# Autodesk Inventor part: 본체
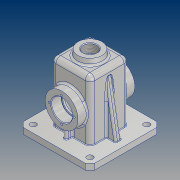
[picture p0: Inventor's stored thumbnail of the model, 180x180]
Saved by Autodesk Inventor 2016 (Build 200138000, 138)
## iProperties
Created: 2018-10
Part Number: 본체
Material: 알루미늄 6061
Document SubType Name: Modeling
Designer: user
Density: 2.7 g/cm^3
Appearance: 알루미늄 - 평지
Mass: 794.228 g
Surface Area: 899.5 cm^2
Volume: 294.158 cm^3
Author: user
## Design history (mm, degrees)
sketch "스케치1"
  geometry: L1 (-60, 60)-(60, 60); L2 (60, 60)-(60, -60); L3 (60, -60)-(-60, -60); L4 (-60, -60)-(-60, 60); L5 (-60, 60)-(60, -60); L6 (60, 60)-(-60, -60); 1 further point
  constraints: 12 end point, 2 midpoint, 2 parallel, 1 horizontal, 1 perpendicular
  dimensions: "d0" = 120 distance of L2.end L3.end; "d1" = 120 distance of L1.end L2.end
extrude "돌출1" new body sketch "스케치1" distance "d2" = 10; taper "d3" = 0 deg
sketch "스케치2"
  geometry: L1 (-32.5, -32.5)-(32.5, -32.5); L2 (32.5, -32.5)-(32.5, 32.5); L3 (32.5, 32.5)-(-32.5, 32.5); L4 (-32.5, 32.5)-(-32.5, -32.5); L5 (-32.5, -32.5)-(32.5, 32.5); L6 (32.5, -32.5)-(-32.5, 32.5); 1 further point
  constraints: 12 end point, 2 midpoint, 2 parallel, 1 horizontal, 1 perpendicular
  dimensions: "d4" = 65 distance of L3.end L2.end; "d5" = 65 distance of L2.end L1.end
extrude "돌출2" join sketch "스케치2" distance "d6" = 100; taper "d7" = 0 deg
feature "쉘1" dims "d8" = 10, "d9" = 5
sketch "스케치3"
  geometry: L1 (92.5, -10)-(-27.5, -10) reference; C1 r 27.5 at (32.5, 45); 2 further points
  constraints: 1 centre point, 1 midpoint, 1 vertical alignment
  dimensions: "d10" = 55 diameter of C1; "d11" = 55 distance from line of L1 C1.centre
extrude "돌출3" join sketch "스케치3" distance "d12" = 15; taper "d13" = 0 deg
sketch "스케치4" dims "d14" = 21
  geometry: C1 r 27.5 at (0, 0) reference; 3 further points
  constraints: 2 vertical alignment, 1 coincident, 2 other
hole "구멍1" sketch "스케치4" diameter "d15" = 30; stored, may be unused: countersink angle "d19" = 90 deg, drill point angle "d21" = 118 deg; dims "d16" = 6, "d17" = 35, "d18" = 17, "d20" = 8
hole "구멍2" sketch "스케치4" diameter "d22" = 3.242; stored, may be unused: countersink angle "d26" = 90 deg, drill point angle "d28" = 118 deg; dims "d23" = 8, "d24" = 35, "d25" = 17, "d27" = 10
node "작업 평면1"
sketch "스케치5"
  geometry: C1 r 20 at (0, 0); 1 further point
  constraints: 1 centre point, 1 coincident
  dimensions: "d33" = 20 radius of C1
extrude "돌출4" join sketch "스케치5" stored distance "d34" = 15; taper "d35" = 7 deg
sketch "스케치6"
  geometry: L1 (10, 48)-(97.905, 32.5); L2 (10, 32.5)-(110, 32.5) reference; L3 (10, -32.5)-(110, -32.5) reference; L4 (10, -60)-(10, 60) reference; L5 (0, 60)-(10, 60) reference; L6 (10, -32.5)-(110, -32.5) reference; L7 (97.905, -32.5)-(10, -48); L8 (0, -60)-(10, -60) reference; 1 further point
  constraints: 4 end point, 4 point on line
  dimensions: "d36" = 12 distance of L4.end L1.start; "d38" = 10 deg angle of L1 L5; "d82" = 12 distance from line of L8 L7.end; "d83" = 10 deg angle of L8 L7
feature "리브1" sketch "스케치6" dims "d39" = 1, "d40" = 10, "d41" = 0, "d42" = 0, "d43" = 1, "d44" = 1
sketch "스케치7"
  geometry: L1 (-42.5, 27.5)-(-42.5, 10); L2 (60, 10)-(-60, 10) reference; L3 (-27.5, 0)-(-27.5, 105) reference; L4 (-37.5, 32.379)-(-36.526, 34) reference; L5 (-36.526, 34)-(-37.5, 35.621) reference; L6 (-37.5, 35.621)-(-47.5, 35.621) reference; L7 (-47.5, 35.621)-(-47.5, 37.5) reference; L8 (-47.5, 37.5)-(-30.5, 37.5) reference; L9 (-30.5, 37.5)-(-30.5, 40) reference; L10 (-30.5, 40)-(-27.5, 40) reference; L11 (-27.5, 40)-(-27.5, 0) reference; L12 (-27.5, 0)-(-60, 0) reference; L13 (-60, 0)-(-60, 10) reference; L14 (-60, 10)-(-32.5, 10) reference; L15 (-32.5, 10)-(-32.5, 27.5) reference; L16 (-32.5, 27.5)-(-47.5, 27.5) reference; L17 (-47.5, 27.5)-(-47.5, 32.379) reference; L18 (-47.5, 32.379)-(-37.5, 32.379) reference; L19 (36.526, 34)-(37.5, 32.379) reference; L20 (37.5, 32.379)-(47.5, 32.379) reference; L21 (47.5, 32.379)-(47.5, 27.5) reference; L22 (47.5, 27.5)-(32.5, 27.5) reference; L23 (32.5, 27.5)-(32.5, 10) reference; L24 (32.5, 10)-(60, 10) reference; L25 (60, 10)-(60, 0) reference; L26 (60, 0)-(27.5, 0) reference; L27 (27.5, 0)-(27.5, 40) reference; L28 (27.5, 40)-(30.5, 40) reference; L29 (30.5, 40)-(30.5, 37.5) reference; L30 (30.5, 37.5)-(47.5, 37.5) reference; L31 (47.5, 37.5)-(47.5, 35.621) reference; L32 (47.5, 35.621)-(37.5, 35.621) reference; L33 (37.5, 35.621)-(36.526, 34) reference; L34 (37.5, 77.621)-(36.526, 76) reference; L35 (36.526, 76)-(37.5, 74.379) reference; L36 (37.5, 74.379)-(47.5, 74.379) reference; L37 (47.5, 74.379)-(47.5, 72.5) reference; L38 (47.5, 72.5)-(30.5, 72.5) reference; L39 (30.5, 72.5)-(30.5, 70) reference; L40 (30.5, 70)-(27.5, 70) reference; L41 (27.5, 70)-(27.5, 105) reference; L42 (27.5, 105)-(-27.5, 105) reference; L43 (-27.5, 105)-(-27.5, 70) reference; L44 (-27.5, 70)-(-30.5, 70) reference; L45 (-30.5, 70)-(-30.5, 72.5) reference; L46 (-30.5, 72.5)-(-47.5, 72.5) reference; L47 (-47.5, 72.5)-(-47.5, 74.379) reference; L48 (-47.5, 74.379)-(-37.5, 74.379) reference; L49 (-37.5, 74.379)-(-36.526, 76) reference; L50 (-36.526, 76)-(-37.5, 77.621) reference; L51 (-37.5, 77.621)-(-47.5, 77.621) reference; L52 (-47.5, 77.621)-(-47.5, 82.5) reference; L53 (-47.5, 82.5)-(-32.5, 82.5) reference; L54 (-32.5, 82.5)-(-32.5, 110) reference; L55 (-32.5, 110)-(-21.228, 110) reference; L56 (-21.228, 110)-(-20, 120) reference; L57 (-20, 120)-(20, 120) reference; L58 (20, 120)-(21.228, 110) reference; L59 (21.228, 110)-(32.5, 110) reference; L60 (32.5, 110)-(32.5, 82.5) reference; L61 (32.5, 82.5)-(47.5, 82.5) reference; L62 (47.5, 82.5)-(47.5, 77.621) reference; L63 (47.5, 77.621)-(37.5, 77.621) reference; 1 further point
  constraints: 2 end point, 2 point on line, 1 vertical
  dimensions: "d45" = 15 distance between parallel lines of L3 L1
feature "리브2" sketch "스케치7" dims "d46" = 1, "d47" = 6, "d48" = 0, "d49" = 0, "d50" = 1, "d51" = 1
sketch "스케치8"
  geometry: C1 r 20 at (0, 0) reference
hole "구멍3" sketch "스케치8" at (0, 0) diameter "d52" = 22.835; stored, may be unused: countersink angle "d56" = 90 deg, drill point angle "d58" = 118 deg; dims "d53" = 50, "d54" = 35, "d55" = 17, "d57" = 59.3
chamfer "모따기1" distance "d59" = 8; stored, may be unused: second distance "d60" = 2, angle "d61" = 45 deg
sketch "스케치9"
  geometry: L1 (-60, 52)-(-60, -52) reference; L2 (52, 60)-(-52, 60) reference; L3 (-60, 0)-(60, 0); L4 (60, 52)-(60, -52) reference; L5 (52, -60)-(-52, -60) reference; L6 (0, -60)-(0, 60); L7 (47.5, -47.5)-(-47.5, -47.5); L8 (-47.5, -47.5)-(-47.5, 47.5); L9 (-47.5, 47.5)-(47.5, 47.5); L10 (47.5, 47.5)-(47.5, -47.5); L11 (47.5, -47.5)-(-47.5, 47.5); L12 (-47.5, -47.5)-(47.5, 47.5); C1 r 5 at (-47.5, -47.5); C2 r 5 at (-47.5, 47.5); C3 r 5 at (47.5, 47.5); C4 r 5 at (47.5, -47.5); 1 further point
  constraints: 16 end point, 6 midpoint, 4 centre point, 4 coincident, 2 parallel, 1 horizontal, 1 perpendicular
  dimensions: "d62" = 95 distance of L8.end L9.end; "d63" = 95 distance of L7.end L8.end; "d64" = 10 diameter of C1; "d65" = 5 radius of C2; "d66" = 5 radius of C3; "d67" = 5 radius of C4
extrude "돌출5" cut sketch "스케치9" stored distance "d68" = 15; taper "d69" = 0 deg
sketch "스케치10"
  geometry: L1 (0, 0)-(0, 100) reference; L2 (8.853, 91.291)-(56.147, 91.291); L3 (56.147, 91.291)-(56.147, 76.709); L4 (56.147, 76.709)-(8.853, 76.709); L5 (8.853, 76.709)-(8.853, 91.291); L6 (8.853, 76.709)-(56.147, 91.291); L7 (12.5, 110)-(52.5, 110) reference; 2 further points
  constraints: 2 end point, 1 midpoint, 2 other
  dimensions: "d70" = 26 distance from line of L7 point (32.5, 84); "d71" = 32.5 distance from line of L1 point (32.5, 84)
feature "엠보싱1" sketch "스케치10" dims "d0" = 120, "d1" = 120, "d72" = 0.5, "d73" = 0
fillet "모깎기1" dims "d74" = 0.3
chamfer "모따기2" distance "d75" = 1; stored, may be unused: second distance "d76" = 2, angle "d77" = 45 deg
fillet "모깎기2" dims "d78" = 8
fillet "모깎기3" dims "d79" = 3
fillet "모깎기4" dims "d80" = 3
fillet "모깎기5" dims "d81" = 1
node "솔리드1"
pattern_circular "원형 패턴1" dims angle "d30" = 360 deg
mirror "대칭1"
mirror "대칭2"
mirror "대칭3"
node "절단 모서리 투영1"
